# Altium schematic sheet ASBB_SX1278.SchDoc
size A4
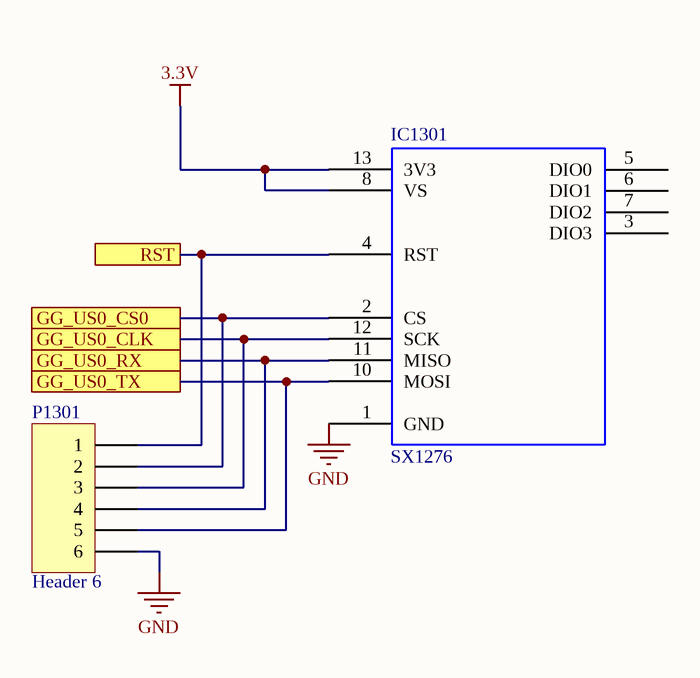
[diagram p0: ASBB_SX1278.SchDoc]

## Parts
IC1301  SX1276  [Modtronix inAir9]
P1301  Header 6  [HDR1X6]

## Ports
GG_US0_CLK, GG_US0_CS0, GG_US0_RX, GG_US0_TX, RST

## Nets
3.3V: IC1301.8(VS) IC1301.13(3V3)
GND: IC1301.1(GND) P1301.6
GG_US0_CLK: IC1301.12(SCK) P1301.3 ; port GG_US0_CLK
GG_US0_CS0: IC1301.2(CS) P1301.2 ; port GG_US0_CS0
GG_US0_RX: IC1301.11(MISO) P1301.4 ; port GG_US0_RX
GG_US0_TX: IC1301.10(MOSI) P1301.5 ; port GG_US0_TX
RST: IC1301.4(RST) P1301.1 ; port RST

Not connected (* = marked no-connect by the designer): IC1301 3(DIO3) 5(DIO0) 6(DIO1) 7(DIO2) 9(NC) 14(NC)

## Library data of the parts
IC1301 = Modtronix inAir9: Modtronix LoRa Transceiver
P1301 = Header 6: Header, 6-Pin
